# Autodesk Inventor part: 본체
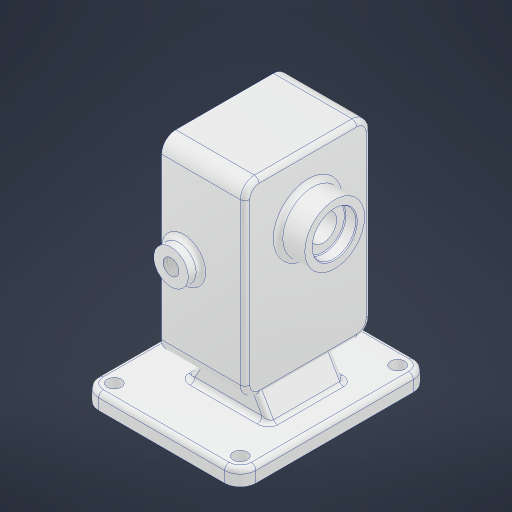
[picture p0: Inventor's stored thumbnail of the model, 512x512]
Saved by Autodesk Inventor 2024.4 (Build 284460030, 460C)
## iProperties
Created: 2026-10
Part Number: 본체
Material: 알루미늄 6061
Document SubType Name: Modeling
Designer: user
Density: 2.7 g/cm^3
Appearance: 알루미늄 - 평지
Mass: 1469.22 g
Surface Area: 818.789 cm^2
Volume: 544.157 cm^3
Author: user
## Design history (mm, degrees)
sketch "스케치1"
  geometry: L1 (50, 60)-(-50, 60); L2 (-50, 60)-(-50, -60); L3 (-50, -60)-(50, -60); L4 (50, -60)-(50, 60); L5 (50, 60)-(-50, -60); L6 (-50, 60)-(50, -60); 1 further point
  constraints: 12 end point, 2 midpoint, 2 parallel, 1 horizontal, 1 perpendicular
  dimensions: "d0" = 100 distance of L3.end L2.end; "d1" = 120 distance of L2.end L1.end
extrude "돌출1" new body sketch "스케치1" distance "d2" = 10; taper "d3" = 0 deg
fillet "모깎기1" dims "d4" = 10
sketch "스케치2"
  geometry: A1 r 10 centre (40, -50) between (40, -60) and (50, -50) reference; A2 r 10 centre (40, 50) between (50, 50) and (40, 60) reference; A3 r 10 centre (-40, 50) between (-40, 60) and (-50, 50) reference; A4 r 10 centre (-40, -50) between (-50, -50) and (-40, -60) reference; 5 further points
  constraints: 4 coincident
hole "구멍1" sketch "스케치2" at (-40, 50), (40, 50), (40, -50), (-40, -50) diameter "d5" = 9; stored, may be unused: countersink angle "d9" = 90 deg, drill point angle "d11" = 118 deg; dims "d6" = 6, "d7" = 4, "d8" = 2, "d10" = 8
fillet "모깎기2" dims "d12" = 3
sketch "스케치3"
  geometry: L1 (-40, 10)-(40, 10) reference; L2 (-20, 10)-(-8.453, 30); L3 (-8.453, 30)-(21.453, 30); L4 (21.453, 30)-(33, 10); L5 (50, 7)-(50, 0) reference; 1 further point
  constraints: 6 end point, 2 point on line, 1 parallel
  dimensions: "d13" = 17 distance from line of L5 L4.end; "d14" = 60 deg angle of L1 L2 (= d15); "d15" = 60 deg angle of L1 L4; "d16" = 53 distance of L4.end L2.start; "d17" = 20 distance between parallel lines of L3 L1
extrude "돌출2" join sketch "스케치3" stored distance "d18" = 48; taper "d19" = 0 deg
sketch "스케치4" dims "d80" = 0.5
  geometry: L1 (0, 0)-(0, 48) reference; L2 (29.906, 0)-(0, 0) reference; L3 (29.906, 48)-(29.906, 0) reference; L4 (0, 48)-(29.906, 48) reference; L5 (-11.547, 64)-(41.453, 64); L6 (41.453, 64)-(41.453, -16); L7 (41.453, -16)-(-11.547, -16); L8 (-11.547, -16)-(-11.547, 64); L9 (-11.547, 0)-(-11.547, 48) reference; 2 further points
  constraints: 8 end point, 2 midpoint, 2 parallel, 1 horizontal, 1 perpendicular
  dimensions: "d20" = 53 distance of L6.end L7.end; "d21" = 80 distance of L5.end L6.end
extrude "돌출3" join sketch "스케치4" distance "d22" = 120; taper "d23" = 0 deg
sketch "스케치5"
  geometry: L1 (0, 120)-(80, 120) reference; L2 (0, 0)-(0, 120) reference; L3 (40, 82)-(40, 38); L4 (16, 82)-(16, 38); L5 (64, 38)-(64, 82); A1 r 24 centre (40, 82) between (64, 82) and (16, 82); A2 r 24 centre (40, 38) between (16, 38) and (64, 38); 6 further points
  constraints: 8 end point, 5 point on circle, 4 midpoint, 4 tangent, 2 centre point, 1 horizontal alignment, 1 parallel, 1 vertical, 1 vertical alignment
  dimensions: "d25" = 24 radius of A1; "d26" = 44 distance of L3.start L3.end
extrude "돌출4" cut sketch "스케치5" distance "d27" = 29; taper "d28" = 0 deg
sketch "스케치6"
  geometry: L1 (0, 0)-(80, 0) reference; L2 (80, 0)-(80, 120) reference; 9 further points
  constraints: 6 vertical alignment, 4 horizontal alignment
  dimensions: "d29" = 62 distance of point (71, 111) point (9, 111); "d30" = 29 distance of point (71, 82) point (71, 111); "d31" = 44 distance of point (71, 38) point (71, 82); "d32" = 29 distance of point (71, 9) point (71, 38) (= d30); "d33" = 9 distance from line of L2 point (71, 9); "d34" = 9 distance from line of L1 point (71, 9) (computed from d32, d30, d31)
hole "구멍2" sketch "스케치6" at (9, 111), (71, 111), (71, 82), (9, 82), (9, 38), (71, 38), (71, 9), (9, 9) diameter "d35" = 4.134; stored, may be unused: countersink angle "d39" = 90 deg, drill point angle "d41" = 118 deg; dims "d36" = 10, "d37" = 4, "d38" = 2, "d40" = 12
fillet "모깎기3" dims "d42" = 9
fillet "모깎기4" dims "d43" = 3
sketch "스케치7"
  geometry: C1 r 12.5 at (40, 82); C2 r 12.5 at (40, 38); A1 r 24 centre (40, 38) between (16, 38) and (64, 38) reference; A2 r 24 centre (40, 82) between (64, 82) and (16, 82) reference; 1 further point
  constraints: 2 centre point, 2 coincident
  dimensions: "d44" = 25 diameter of C1; "d45" = 25 diameter of C2
extrude "돌출5" cut sketch "스케치7" distance "d46" = 15; taper "d47" = 0 deg
sketch "스케치8"
  geometry: C1 r 12.5 at (0, 0) reference; C2 r 8.5 at (0, 0); 1 further point
  constraints: 1 centre point, 1 coincident
  dimensions: "d48" = 17 diameter of C2
extrude "돌출6" cut sketch "스케치8" extent not by distance; stored distance "d49" = 0; taper "d50" = 0 deg
sketch "스케치9"
  geometry: C1 r 8.5 at (37, 73) reference; C2 r 19 at (37, 73); 1 further point
  constraints: 1 centre point, 1 coincident
  dimensions: "d51" = 38 diameter of C2
extrude "돌출7" join sketch "스케치9" distance "d52" = 17; taper "d53" = 0 deg
sketch "스케치10"
  geometry: C1 r 8.5 at (0, 0) reference; C2 r 14 at (0, 0); 1 further point
  constraints: 1 centre point, 1 coincident
  dimensions: "d54" = 28 diameter of C2
extrude "돌출8" cut sketch "스케치10" distance "d55" = 7.3; taper "d56" = 0 deg
sketch "스케치11"
  geometry: L1 (0, 0)-(0, 102) reference; C1 r 11 at (14, 51); 2 further points
  constraints: 1 centre point, 1 horizontal alignment, 1 midpoint
  dimensions: "d57" = 22 diameter of C1; "d58" = 14 distance from line of C1.centre L1
extrude "돌출9" join sketch "스케치11" distance "d59" = 8; taper "d60" = 0 deg
sketch "스케치12"
  geometry: C1 r 11 at (0, 0) reference; 2 further points
  constraints: 1 coincident
sketch "스케치13"
  geometry: C1 r 11 at (0, 0) reference; 2 further points
  constraints: 1 coincident
hole "구멍3" sketch "스케치12" diameter "d61" = 10.106; stored, may be unused: countersink angle "d65" = 90 deg, drill point angle "d67" = 118 deg; dims "d62" = 8, "d63" = 4, "d64" = 2, "d66" = 32.3
hole "구멍4" sketch "스케치13" diameter "d68" = 10.106; stored, may be unused: countersink angle "d72" = 90 deg, drill point angle "d74" = 118 deg; dims "d69" = 8, "d70" = 4, "d71" = 2, "d73" = 8
fillet "모깎기5" dims "d75" = 3
fillet "모깎기6" dims "d76" = 3
chamfer "모따기1" distance "d77" = 1; stored, may be unused: second distance "d78" = 2, angle "d79" = 45 deg
fillet "모깎기7" dims "d80" = 0.5
chamfer "모따기2" distance "d81" = 0.7; stored, may be unused: second distance "d82" = 2, angle "d83" = 30 deg
fillet "모깎기8" dims "d84" = 3
fillet "모깎기9" dims "d85" = 3
node "솔리드1"
mirror "미러1"
feature "A9D066F2-1C7D-4E18-AEED-F7BC21143FA4" dims "d5" = 9, "d6" = 6, "d7" = 4, "d8" = 2, "d9" = 90 deg, "d10" = 8, "d11" = 118 deg
